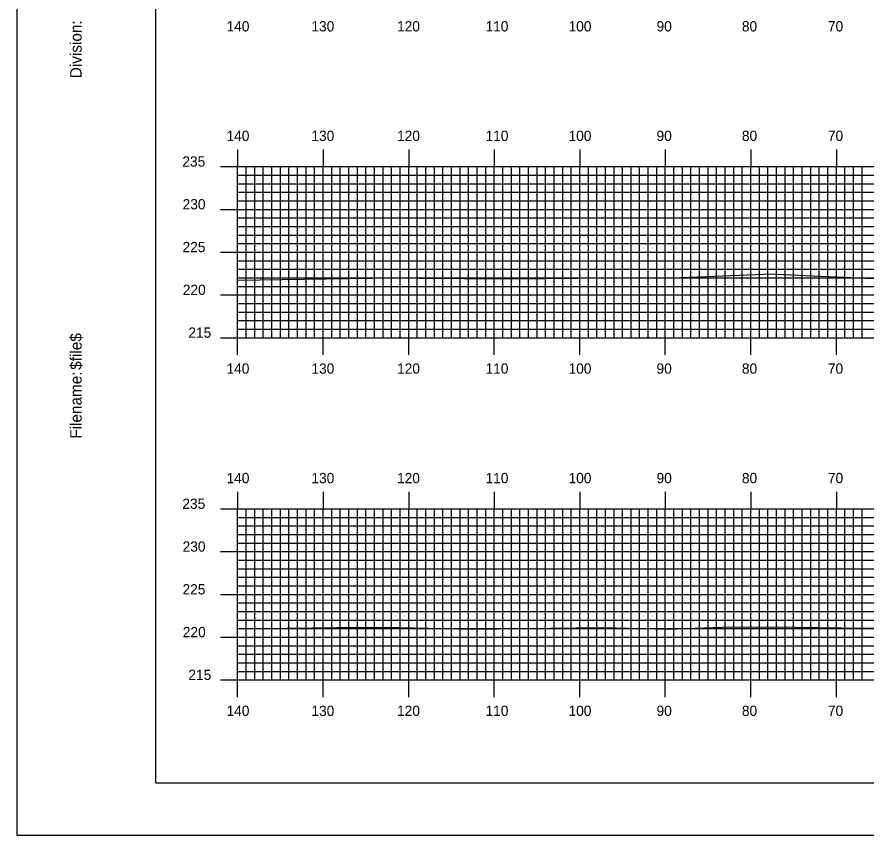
# Model space of a CAD drawing. Extents: x 1804684 to 1805027, y 442591 to 442811.
# Drawn here: x 1804683.9 to 1804783.1, y 442590.5 to 442686.2 of the extents above; entities that cross this region are included whole.
import ezdxf

# ---------------------------------------------------------------- set-up
doc = ezdxf.new("R2010")
doc.units = 0
for name, color, linetype in [('BORDER', 7, 'Continuous'), ('H_V ANNOTATION', 7, 'Continuous'), ('MAJOR', 7, 'Continuous'), ('MINOR', 7, 'Continuous'), ('PLOT BOUNDARY', 7, 'Continuous'), ('S_Roadway_Centerline', 7, 'Continuous')]:
    doc.layers.add(name, color=color, linetype=linetype)

msp = doc.modelspace()

# ---------------------------------------------------------------- linework, layer by layer
at = {"layer": 'BORDER'}
msp.add_lwpolyline([(1804700.08, 442596.665), (1805020.08, 442596.665), (1805020.08, 442806.665), (1804700.08, 442806.665)], close=True, dxfattribs=at)
at = {"layer": 'MAJOR'}
for p, q in [((1804709.68, 442670.669), (1804709.68, 442668.665)), ((1804719.68, 442670.669), (1804719.68, 442668.665)), ((1804729.68, 442670.669), (1804729.68, 442668.665)), ((1804739.68, 442670.669), (1804739.68, 442668.665)), ((1804749.68, 442670.669), (1804749.68, 442668.665)), ((1804759.68, 442670.669), (1804759.68, 442668.665)), ((1804769.68, 442670.669), (1804769.68, 442668.665)), ((1804779.68, 442670.669), (1804779.68, 442668.665)), ((1804707.676, 442668.665), (1804709.68, 442668.665)), ((1804709.68, 442668.665), (1804989.68, 442668.665)), ((1804709.68, 442648.665), (1804709.68, 442668.665)), ((1804709.68, 442648.665), (1804709.68, 442668.665)), ((1804709.68, 442668.665), (1804989.68, 442668.665)), ((1804719.68, 442648.665), (1804719.68, 442668.665)), ((1804729.68, 442648.665), (1804729.68, 442668.665)), ((1804739.68, 442648.665), (1804739.68, 442668.665)), ((1804749.68, 442648.665), (1804749.68, 442668.665)), ((1804759.68, 442648.665), (1804759.68, 442668.665)), ((1804769.68, 442648.665), (1804769.68, 442668.665)), ((1804779.68, 442648.665), (1804779.68, 442668.665)), ((1804707.676, 442663.665), (1804709.68, 442663.665)), ((1804709.68, 442663.665), (1804989.68, 442663.665)), ((1804707.676, 442658.665), (1804709.68, 442658.665)), ((1804709.68, 442658.665), (1804989.68, 442658.665)), ((1804707.676, 442653.665), (1804709.68, 442653.665)), ((1804709.68, 442653.665), (1804989.68, 442653.665)), ((1804707.676, 442648.665), (1804709.68, 442648.665)), ((1804709.68, 442648.665), (1804989.68, 442648.665)), ((1804709.68, 442648.665), (1804989.68, 442648.665)), ((1804709.68, 442646.661), (1804709.68, 442648.665)), ((1804719.68, 442646.661), (1804719.68, 442648.665)), ((1804729.68, 442646.661), (1804729.68, 442648.665)), ((1804739.68, 442646.661), (1804739.68, 442648.665)), ((1804749.68, 442646.661), (1804749.68, 442648.665)), ((1804759.68, 442646.661), (1804759.68, 442648.665)), ((1804769.68, 442646.661), (1804769.68, 442648.665)), ((1804779.68, 442646.661), (1804779.68, 442648.665)), ((1804709.68, 442630.669), (1804709.68, 442628.665)), ((1804719.68, 442630.669), (1804719.68, 442628.665)), ((1804729.68, 442630.669), (1804729.68, 442628.665)), ((1804739.68, 442630.669), (1804739.68, 442628.665)), ((1804749.68, 442630.669), (1804749.68, 442628.665)), ((1804759.68, 442630.669), (1804759.68, 442628.665)), ((1804769.68, 442630.669), (1804769.68, 442628.665)), ((1804779.68, 442630.669), (1804779.68, 442628.665)), ((1804707.676, 442628.665), (1804709.68, 442628.665)), ((1804709.68, 442628.665), (1804989.68, 442628.665)), ((1804709.68, 442608.665), (1804709.68, 442628.665)), ((1804709.68, 442608.665), (1804709.68, 442628.665)), ((1804709.68, 442628.665), (1804989.68, 442628.665)), ((1804719.68, 442608.665), (1804719.68, 442628.665)), ((1804729.68, 442608.665), (1804729.68, 442628.665)), ((1804739.68, 442608.665), (1804739.68, 442628.665)), ((1804749.68, 442608.665), (1804749.68, 442628.665)), ((1804759.68, 442608.665), (1804759.68, 442628.665)), ((1804769.68, 442608.665), (1804769.68, 442628.665)), ((1804779.68, 442608.665), (1804779.68, 442628.665)), ((1804707.676, 442623.665), (1804709.68, 442623.665)), ((1804709.68, 442623.665), (1804989.68, 442623.665)), ((1804707.676, 442618.665), (1804709.68, 442618.665)), ((1804709.68, 442618.665), (1804989.68, 442618.665)), ((1804707.676, 442613.665), (1804709.68, 442613.665)), ((1804709.68, 442613.665), (1804989.68, 442613.665)), ((1804707.676, 442608.665), (1804709.68, 442608.665)), ((1804709.68, 442608.665), (1804989.68, 442608.665)), ((1804709.68, 442608.665), (1804989.68, 442608.665)), ((1804709.68, 442606.661), (1804709.68, 442608.665)), ((1804719.68, 442606.661), (1804719.68, 442608.665)), ((1804729.68, 442606.661), (1804729.68, 442608.665)), ((1804739.68, 442606.661), (1804739.68, 442608.665)), ((1804749.68, 442606.661), (1804749.68, 442608.665)), ((1804759.68, 442606.661), (1804759.68, 442608.665)), ((1804769.68, 442606.661), (1804769.68, 442608.665)), ((1804779.68, 442606.661), (1804779.68, 442608.665))]:
    msp.add_line(p, q, dxfattribs=at)
at = {"layer": 'MINOR'}
for p, q in [((1804710.68, 442648.665), (1804710.68, 442668.665)), ((1804711.68, 442648.665), (1804711.68, 442668.665)), ((1804712.68, 442648.665), (1804712.68, 442668.665)), ((1804713.68, 442648.665), (1804713.68, 442668.665)), ((1804714.68, 442648.665), (1804714.68, 442668.665)), ((1804715.68, 442648.665), (1804715.68, 442668.665)), ((1804716.68, 442648.665), (1804716.68, 442668.665)), ((1804717.68, 442648.665), (1804717.68, 442668.665)), ((1804718.68, 442648.665), (1804718.68, 442668.665)), ((1804720.68, 442648.665), (1804720.68, 442668.665)), ((1804721.68, 442648.665), (1804721.68, 442668.665)), ((1804722.68, 442648.665), (1804722.68, 442668.665)), ((1804723.68, 442648.665), (1804723.68, 442668.665)), ((1804724.68, 442648.665), (1804724.68, 442668.665)), ((1804725.68, 442648.665), (1804725.68, 442668.665)), ((1804726.68, 442648.665), (1804726.68, 442668.665)), ((1804727.68, 442648.665), (1804727.68, 442668.665)), ((1804728.68, 442648.665), (1804728.68, 442668.665)), ((1804730.68, 442648.665), (1804730.68, 442668.665)), ((1804731.68, 442648.665), (1804731.68, 442668.665)), ((1804732.68, 442648.665), (1804732.68, 442668.665)), ((1804733.68, 442648.665), (1804733.68, 442668.665)), ((1804734.68, 442648.665), (1804734.68, 442668.665)), ((1804735.68, 442648.665), (1804735.68, 442668.665)), ((1804736.68, 442648.665), (1804736.68, 442668.665)), ((1804737.68, 442648.665), (1804737.68, 442668.665)), ((1804738.68, 442648.665), (1804738.68, 442668.665)), ((1804740.68, 442648.665), (1804740.68, 442668.665)), ((1804741.68, 442648.665), (1804741.68, 442668.665)), ((1804742.68, 442648.665), (1804742.68, 442668.665)), ((1804743.68, 442648.665), (1804743.68, 442668.665)), ((1804744.68, 442648.665), (1804744.68, 442668.665)), ((1804745.68, 442648.665), (1804745.68, 442668.665)), ((1804746.68, 442648.665), (1804746.68, 442668.665)), ((1804747.68, 442648.665), (1804747.68, 442668.665)), ((1804748.68, 442648.665), (1804748.68, 442668.665)), ((1804750.68, 442648.665), (1804750.68, 442668.665)), ((1804751.68, 442648.665), (1804751.68, 442668.665)), ((1804752.68, 442648.665), (1804752.68, 442668.665)), ((1804753.68, 442648.665), (1804753.68, 442668.665)), ((1804754.68, 442648.665), (1804754.68, 442668.665)), ((1804755.68, 442648.665), (1804755.68, 442668.665)), ((1804756.68, 442648.665), (1804756.68, 442668.665)), ((1804757.68, 442648.665), (1804757.68, 442668.665)), ((1804758.68, 442648.665), (1804758.68, 442668.665)), ((1804760.68, 442648.665), (1804760.68, 442668.665)), ((1804761.68, 442648.665), (1804761.68, 442668.665)), ((1804762.68, 442648.665), (1804762.68, 442668.665)), ((1804763.68, 442648.665), (1804763.68, 442668.665)), ((1804764.68, 442648.665), (1804764.68, 442668.665)), ((1804765.68, 442648.665), (1804765.68, 442668.665)), ((1804766.68, 442648.665), (1804766.68, 442668.665)), ((1804767.68, 442648.665), (1804767.68, 442668.665)), ((1804768.68, 442648.665), (1804768.68, 442668.665)), ((1804770.68, 442648.665), (1804770.68, 442668.665)), ((1804771.68, 442648.665), (1804771.68, 442668.665)), ((1804772.68, 442648.665), (1804772.68, 442668.665)), ((1804773.68, 442648.665), (1804773.68, 442668.665)), ((1804774.68, 442648.665), (1804774.68, 442668.665)), ((1804775.68, 442648.665), (1804775.68, 442668.665)), ((1804776.68, 442648.665), (1804776.68, 442668.665)), ((1804777.68, 442648.665), (1804777.68, 442668.665)), ((1804778.68, 442648.665), (1804778.68, 442668.665)), ((1804780.68, 442648.665), (1804780.68, 442668.665)), ((1804781.68, 442648.665), (1804781.68, 442668.665)), ((1804782.68, 442648.665), (1804782.68, 442668.665)), ((1804709.68, 442667.665), (1804989.68, 442667.665)), ((1804709.68, 442667.665), (1804711.684, 442667.665)), ((1804709.68, 442666.665), (1804989.68, 442666.665)), ((1804709.68, 442666.665), (1804711.684, 442666.665)), ((1804709.68, 442665.665), (1804989.68, 442665.665)), ((1804709.68, 442665.665), (1804711.684, 442665.665)), ((1804709.68, 442664.665), (1804989.68, 442664.665)), ((1804709.68, 442664.665), (1804711.684, 442664.665)), ((1804709.68, 442662.665), (1804989.68, 442662.665)), ((1804709.68, 442662.665), (1804711.684, 442662.665)), ((1804709.68, 442661.665), (1804989.68, 442661.665)), ((1804709.68, 442661.665), (1804711.684, 442661.665)), ((1804709.68, 442660.665), (1804989.68, 442660.665)), ((1804709.68, 442660.665), (1804711.684, 442660.665)), ((1804709.68, 442659.665), (1804989.68, 442659.665)), ((1804709.68, 442659.665), (1804711.684, 442659.665)), ((1804709.68, 442657.665), (1804989.68, 442657.665)), ((1804709.68, 442657.665), (1804711.684, 442657.665)), ((1804709.68, 442656.665), (1804989.68, 442656.665)), ((1804709.68, 442656.665), (1804711.684, 442656.665)), ((1804709.68, 442655.665), (1804989.68, 442655.665)), ((1804709.68, 442655.665), (1804711.684, 442655.665)), ((1804709.68, 442654.665), (1804989.68, 442654.665)), ((1804709.68, 442654.665), (1804711.684, 442654.665)), ((1804709.68, 442652.665), (1804989.68, 442652.665)), ((1804709.68, 442652.665), (1804711.684, 442652.665)), ((1804709.68, 442651.665), (1804989.68, 442651.665)), ((1804709.68, 442651.665), (1804711.684, 442651.665)), ((1804709.68, 442650.665), (1804989.68, 442650.665)), ((1804709.68, 442650.665), (1804711.684, 442650.665)), ((1804709.68, 442649.665), (1804989.68, 442649.665)), ((1804709.68, 442649.665), (1804711.684, 442649.665)), ((1804710.68, 442608.665), (1804710.68, 442628.665)), ((1804711.68, 442608.665), (1804711.68, 442628.665)), ((1804712.68, 442608.665), (1804712.68, 442628.665)), ((1804713.68, 442608.665), (1804713.68, 442628.665)), ((1804714.68, 442608.665), (1804714.68, 442628.665)), ((1804715.68, 442608.665), (1804715.68, 442628.665)), ((1804716.68, 442608.665), (1804716.68, 442628.665)), ((1804717.68, 442608.665), (1804717.68, 442628.665)), ((1804718.68, 442608.665), (1804718.68, 442628.665)), ((1804720.68, 442608.665), (1804720.68, 442628.665)), ((1804721.68, 442608.665), (1804721.68, 442628.665)), ((1804722.68, 442608.665), (1804722.68, 442628.665)), ((1804723.68, 442608.665), (1804723.68, 442628.665)), ((1804724.68, 442608.665), (1804724.68, 442628.665)), ((1804725.68, 442608.665), (1804725.68, 442628.665)), ((1804726.68, 442608.665), (1804726.68, 442628.665)), ((1804727.68, 442608.665), (1804727.68, 442628.665)), ((1804728.68, 442608.665), (1804728.68, 442628.665)), ((1804730.68, 442608.665), (1804730.68, 442628.665)), ((1804731.68, 442608.665), (1804731.68, 442628.665)), ((1804732.68, 442608.665), (1804732.68, 442628.665)), ((1804733.68, 442608.665), (1804733.68, 442628.665)), ((1804734.68, 442608.665), (1804734.68, 442628.665)), ((1804735.68, 442608.665), (1804735.68, 442628.665)), ((1804736.68, 442608.665), (1804736.68, 442628.665)), ((1804737.68, 442608.665), (1804737.68, 442628.665)), ((1804738.68, 442608.665), (1804738.68, 442628.665)), ((1804740.68, 442608.665), (1804740.68, 442628.665)), ((1804741.68, 442608.665), (1804741.68, 442628.665)), ((1804742.68, 442608.665), (1804742.68, 442628.665)), ((1804743.68, 442608.665), (1804743.68, 442628.665)), ((1804744.68, 442608.665), (1804744.68, 442628.665)), ((1804745.68, 442608.665), (1804745.68, 442628.665)), ((1804746.68, 442608.665), (1804746.68, 442628.665)), ((1804747.68, 442608.665), (1804747.68, 442628.665)), ((1804748.68, 442608.665), (1804748.68, 442628.665)), ((1804750.68, 442608.665), (1804750.68, 442628.665)), ((1804751.68, 442608.665), (1804751.68, 442628.665)), ((1804752.68, 442608.665), (1804752.68, 442628.665)), ((1804753.68, 442608.665), (1804753.68, 442628.665)), ((1804754.68, 442608.665), (1804754.68, 442628.665)), ((1804755.68, 442608.665), (1804755.68, 442628.665)), ((1804756.68, 442608.665), (1804756.68, 442628.665)), ((1804757.68, 442608.665), (1804757.68, 442628.665)), ((1804758.68, 442608.665), (1804758.68, 442628.665)), ((1804760.68, 442608.665), (1804760.68, 442628.665)), ((1804761.68, 442608.665), (1804761.68, 442628.665)), ((1804762.68, 442608.665), (1804762.68, 442628.665)), ((1804763.68, 442608.665), (1804763.68, 442628.665)), ((1804764.68, 442608.665), (1804764.68, 442628.665)), ((1804765.68, 442608.665), (1804765.68, 442628.665)), ((1804766.68, 442608.665), (1804766.68, 442628.665)), ((1804767.68, 442608.665), (1804767.68, 442628.665)), ((1804768.68, 442608.665), (1804768.68, 442628.665)), ((1804770.68, 442608.665), (1804770.68, 442628.665)), ((1804771.68, 442608.665), (1804771.68, 442628.665)), ((1804772.68, 442608.665), (1804772.68, 442628.665)), ((1804773.68, 442608.665), (1804773.68, 442628.665)), ((1804774.68, 442608.665), (1804774.68, 442628.665)), ((1804775.68, 442608.665), (1804775.68, 442628.665)), ((1804776.68, 442608.665), (1804776.68, 442628.665)), ((1804777.68, 442608.665), (1804777.68, 442628.665)), ((1804778.68, 442608.665), (1804778.68, 442628.665)), ((1804780.68, 442608.665), (1804780.68, 442628.665)), ((1804781.68, 442608.665), (1804781.68, 442628.665)), ((1804782.68, 442608.665), (1804782.68, 442628.665)), ((1804709.68, 442627.665), (1804989.68, 442627.665)), ((1804709.68, 442627.665), (1804711.684, 442627.665)), ((1804709.68, 442626.665), (1804989.68, 442626.665)), ((1804709.68, 442626.665), (1804711.684, 442626.665)), ((1804709.68, 442625.665), (1804989.68, 442625.665)), ((1804709.68, 442625.665), (1804711.684, 442625.665)), ((1804709.68, 442624.665), (1804989.68, 442624.665)), ((1804709.68, 442624.665), (1804711.684, 442624.665)), ((1804709.68, 442622.665), (1804989.68, 442622.665)), ((1804709.68, 442622.665), (1804711.684, 442622.665)), ((1804709.68, 442621.665), (1804989.68, 442621.665)), ((1804709.68, 442621.665), (1804711.684, 442621.665)), ((1804709.68, 442620.665), (1804989.68, 442620.665)), ((1804709.68, 442620.665), (1804711.684, 442620.665)), ((1804709.68, 442619.665), (1804989.68, 442619.665)), ((1804709.68, 442619.665), (1804711.684, 442619.665)), ((1804709.68, 442617.665), (1804989.68, 442617.665)), ((1804709.68, 442617.665), (1804711.684, 442617.665)), ((1804709.68, 442616.665), (1804989.68, 442616.665)), ((1804709.68, 442616.665), (1804711.684, 442616.665)), ((1804709.68, 442615.665), (1804989.68, 442615.665)), ((1804709.68, 442615.665), (1804711.684, 442615.665)), ((1804709.68, 442614.665), (1804989.68, 442614.665)), ((1804709.68, 442614.665), (1804711.684, 442614.665)), ((1804709.68, 442612.665), (1804989.68, 442612.665)), ((1804709.68, 442612.665), (1804711.684, 442612.665)), ((1804709.68, 442611.665), (1804989.68, 442611.665)), ((1804709.68, 442611.665), (1804711.684, 442611.665)), ((1804709.68, 442610.665), (1804989.68, 442610.665)), ((1804709.68, 442610.665), (1804711.684, 442610.665)), ((1804709.68, 442609.665), (1804989.68, 442609.665)), ((1804709.68, 442609.665), (1804711.684, 442609.665))]:
    msp.add_line(p, q, dxfattribs=at)
at = {"layer": 'PLOT BOUNDARY'}
msp.add_lwpolyline([(1804683.894, 442590.547), (1805023.894, 442590.547), (1805023.894, 442810.547), (1804683.894, 442810.547)], close=True, dxfattribs=at)
at = {"layer": 'S_Roadway_Centerline'}
for points in [[(1804709.68, 442655.376), (1804725.278, 442655.646), (1804725.4, 442655.645), (1804725.512, 442655.648), (1804741.445, 442655.554), (1804749.469, 442655.61), (1804760.525, 442655.651), (1804772.181, 442656.117), (1804772.616, 442656.11), (1804784.021, 442655.571)], [(1804709.68, 442614.649), (1804721.275, 442614.783), (1804728.58, 442614.818), (1804737.198, 442614.622), (1804752.288, 442614.809), (1804760.006, 442614.623), (1804767.386, 442614.872), (1804774.933, 442614.821), (1804783.042, 442614.738), (1804791.17, 442614.815)]]:
    msp.add_lwpolyline(points, dxfattribs=at)

# ---------------------------------------------------------------- texts
at = {"layer": 'BORDER'}
for s, p in [('Division:', (1804691.45, 442678.997)), ('$file$', (1804691.45, 442644.916)), ('Filename:', (1804691.45, 442636.862))]:
    msp.add_text(s, height=1.3392, rotation=90, dxfattribs=at).set_placement(p)
at = {"layer": 'H_V ANNOTATION'}
for s, p in [('140', (1804708.385, 442684.465)), ('130', (1804718.31, 442684.465)), ('120', (1804728.321, 442684.465)), ('110', (1804738.663, 442684.465)), ('100', (1804748.364, 442684.465)), ('90', (1804758.653, 442684.465)), ('80', (1804768.631, 442684.465)), ('70', (1804778.684, 442684.465)), ('140', (1804708.385, 442671.665)), ('130', (1804718.31, 442671.665)), ('120', (1804728.321, 442671.665)), ('110', (1804738.663, 442671.665)), ('100', (1804748.364, 442671.665)), ('90', (1804758.653, 442671.665)), ('80', (1804768.631, 442671.665)), ('70', (1804778.684, 442671.665)), ('235', (1804703.223, 442668.665)), ('230', (1804703.255, 442663.665)), ('225', (1804703.244, 442658.665)), ('220', (1804703.276, 442653.665)), ('215', (1804703.929, 442648.665)), ('140', (1804708.385, 442644.465)), ('130', (1804718.31, 442644.465)), ('120', (1804728.321, 442644.465)), ('110', (1804738.663, 442644.465)), ('100', (1804748.364, 442644.465)), ('90', (1804758.653, 442644.465)), ('80', (1804768.631, 442644.465)), ('70', (1804778.684, 442644.465)), ('140', (1804708.385, 442631.665)), ('130', (1804718.31, 442631.665)), ('120', (1804728.321, 442631.665)), ('110', (1804738.663, 442631.665)), ('100', (1804748.364, 442631.665)), ('90', (1804758.653, 442631.665)), ('80', (1804768.631, 442631.665)), ('70', (1804778.684, 442631.665)), ('235', (1804703.223, 442628.665)), ('230', (1804703.255, 442623.665)), ('225', (1804703.244, 442618.665)), ('220', (1804703.276, 442613.665)), ('215', (1804703.929, 442608.665)), ('140', (1804708.385, 442604.465)), ('130', (1804718.31, 442604.465)), ('120', (1804728.321, 442604.465)), ('110', (1804738.663, 442604.465)), ('100', (1804748.364, 442604.465)), ('90', (1804758.653, 442604.465)), ('80', (1804768.631, 442604.465)), ('70', (1804778.684, 442604.465))]:
    msp.add_text(s, height=1.2, dxfattribs=at).set_placement(p)
at = {"layer": 'MAJOR'}
for p in [(1804709.671, 442648.665), (1804709.671, 442608.665)]:
    msp.add_text('-', height=0.012, dxfattribs=at).set_placement(p)

doc.saveas('drawing.dxf')
